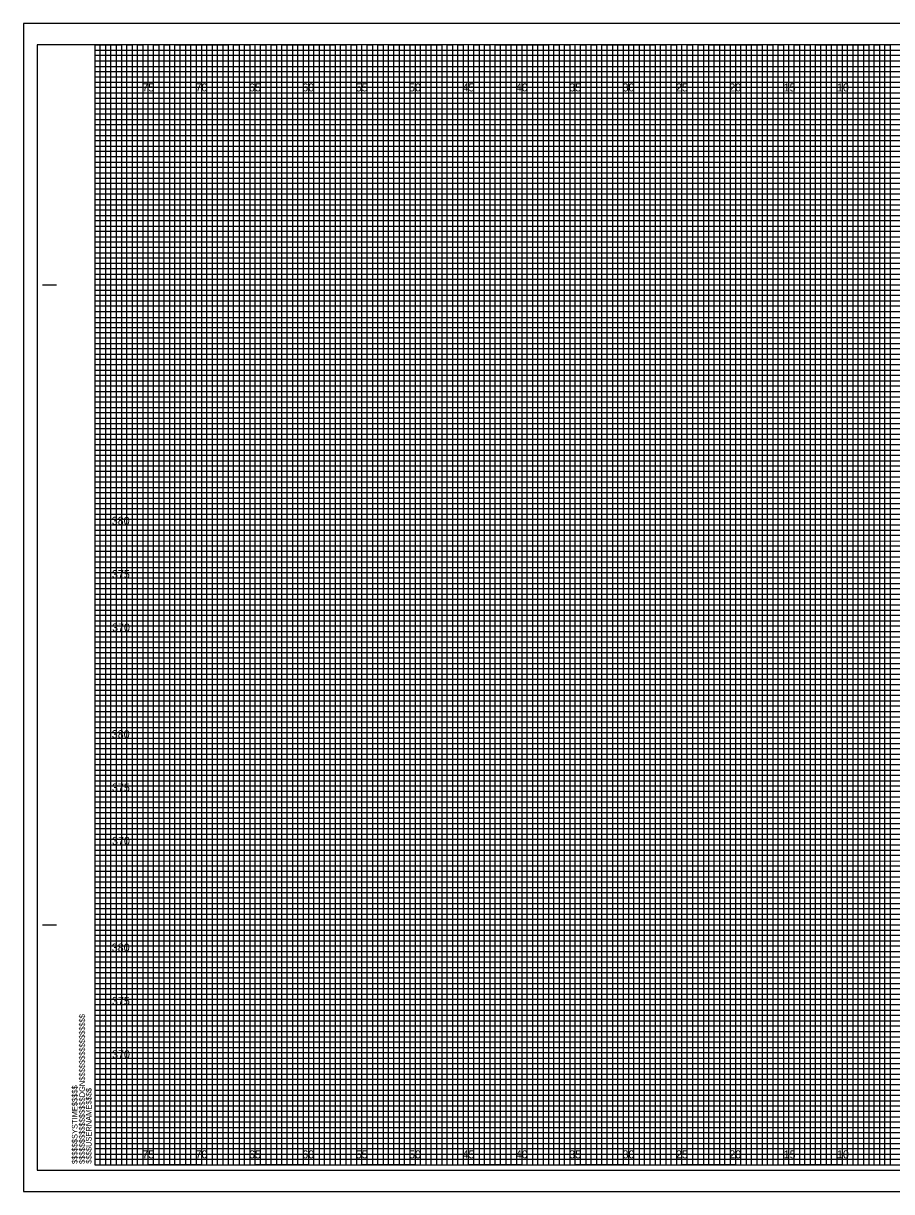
# Model space of a CAD drawing. Extents: x -7 to 162, y -2 to 327.
# Drawn here: x -6.7 to 74.6, y 217.5 to 327 of the extents above; entities that cross this region are included whole.
import ezdxf

# ---------------------------------------------------------------- set-up
doc = ezdxf.new("R2010")
doc.units = 0
for name, color, linetype in [('Exist Cross Section Cell', 7, 'Continuous'), ('Prop CMT Pvmt Course 1', 7, 'Continuous'), ('Prop CMT Pvmt Course 3', 7, 'Continuous'), ('Prop CMT Shld Paved Course 1', 7, 'Continuous'), ('Prop CMT Shld Paved Course 2', 7, 'Continuous'), ('Prop CMT Shld Paved Course 3', 7, 'Continuous'), ('Prop CMT Slope Grass', 7, 'Continuous'), ('Prop CMT Subgrade Earthwork', 7, 'Continuous'), ('Scratch_Level_3', 7, 'Continuous')]:
    doc.layers.add(name, color=color, linetype=linetype)

msp = doc.modelspace()

# ---------------------------------------------------------------- linework, layer by layer
at = {"layer": 'Prop CMT Pvmt Course 3'}
msp.add_lwpolyline([(-6.7, 217.5), (161.65, 217.5), (161.65, 327), (-6.7, 327)], close=True, dxfattribs=at)
at = {"layer": 'Prop CMT Shld Paved Course 1'}
for p, q in [((0, 324.5), (110.95, 324.5)), ((110.95, 323.99), (0, 323.99)), ((0, 323.99), (0, 323.5)), ((0, 323.5), (110.95, 323.5)), ((110.95, 322.94), (0, 322.94)), ((0, 322.94), (0, 322)), ((0, 322), (160, 322))]:
    msp.add_line(p, q, dxfattribs=at)
for points in [[(0, 321.5), (135, 321.5), (160, 321.5)], [(160, 321), (0, 321)], [(0, 320.5), (160, 320.5)], [(160, 319.5), (0, 319.5)], [(0, 319), (160, 319)], [(160, 318.5), (0, 318.49)], [(0, 318), (160, 318)], [(160, 317), (0, 317)], [(0, 316.5), (160, 316.5), (160, 316), (0, 316)], [(0, 315.5), (160, 315.5), (160, 314.5), (0, 314.5)], [(0, 314), (160, 314), (160, 313.5), (0, 313.5)], [(0, 313), (160, 313), (160, 312), (0, 312)], [(0, 311.5), (160, 311.5), (160, 311), (0, 311)], [(0, 310.5), (160, 310.5), (160, 309.5), (0, 309.5)], [(0, 309), (160, 309), (160, 308.5), (0, 308.5)], [(0, 308), (160, 308), (160, 306.97), (160, 306.5), (160, 306), (0, 306)], [(0, 307), (160, 307), (160, 306.5), (0, 306.5)], [(0, 305.5), (160, 305.5), (160, 304.5), (0, 304.51)], [(0, 304.51), (160, 304.5), (160, 304), (0, 304)], [(0, 303.5), (160, 303.5), (160, 303), (0, 303)], [(0, 302), (160, 302), (160, 301.5), (0, 301.5)], [(0, 301), (160, 301), (160, 300.5), (0, 300.5)], [(-0.04, 299.44), (160, 299.44), (160, 298.94), (-0.04, 298.94)], [(0, 298.5), (160, 298.5), (160, 298), (0, 298)], [(0, 297), (160, 297), (160, 296.5), (0, 296.5)], [(0, 296), (160, 296), (160, 295.5), (0, 295.5)], [(0, 294.5), (160, 294.5), (160, 294), (0, 294)], [(0, 293.5), (160, 293.5), (160, 293), (0, 293)], [(0, 292), (160, 292), (160, 291.5), (0, 291.5)], [(0, 291), (160, 291), (160, 290.5), (0, 290.5)], [(0, 289.5), (160, 289.5), (159.99, 288.99), (0, 289)], [(0, 288.5), (160, 288.5), (160, 288), (0, 288)], [(0, 287), (160, 287), (160, 286.5), (0, 286.5)], [(0, 286), (160, 286), (160, 285.5), (0, 285.5)], [(0, 284.5), (160, 284.5), (160, 284), (0, 284)], [(0, 283.5), (160, 283.5), (160, 283), (0, 283)], [(0, 282), (160, 282), (160, 281.5), (0, 281.5)], [(0, 281), (160, 281), (160, 280.5), (0, 280.5)], [(0, 279.5), (160, 279.5), (160, 279), (0, 279)], [(0, 278.5), (160.03, 278.45), (160, 278), (0, 278)], [(0, 277), (160, 277), (160, 276.5), (0, 276.5)], [(0, 276), (160, 276), (160, 275.5), (0, 275.5)], [(0, 274.5), (160, 274.5), (160, 274), (0, 274)], [(0, 273.5), (160, 273.5), (160, 273), (0, 273)], [(0, 272), (160, 272), (160, 271.5), (0, 271.5)], [(0, 271), (160, 271), (160, 270.5), (0, 270.5)], [(0, 269.5), (160, 269.5), (160, 269), (0, 269)], [(0, 268.5), (160, 268.5), (160, 268), (0, 268)], [(0, 267), (160, 267), (160, 266.5), (0, 266.5)], [(0, 266), (160, 266), (160, 265.5), (0, 265.5)], [(0, 264.5), (160, 264.5), (160, 264), (0, 264)], [(0, 263.5), (160, 263.5), (160, 263), (0, 263)], [(0, 262), (160, 262), (160, 261.5), (0, 261.5)], [(0, 261), (160, 261), (160, 260.5), (0, 260.5)], [(0, 259.5), (160, 259.5), (159.99, 258.99), (0, 259)], [(0, 258.5), (160, 258.5), (160, 258), (0, 258)], [(0, 257), (160, 257), (160, 256.5), (0, 256.5)], [(0, 256), (160, 256), (160, 255.5), (0, 255.5)], [(0, 254.5), (160, 254.5), (160, 254), (0, 254)], [(0, 253.5), (160, 253.5), (160, 253), (0, 253)], [(0, 252), (160, 252), (160, 251.5), (0, 251.5)], [(0, 251), (160, 251), (160, 250.5), (0, 250.5)], [(0, 249.5), (160, 249.5), (160, 249), (0, 249)], [(0, 248.5), (160.03, 248.46), (160, 248), (0, 248)], [(0, 247), (160, 247), (160, 246.5), (0, 246.5)], [(0, 246), (160, 246), (160, 245.5), (0, 245.5)], [(0, 244.5), (160, 244.5), (160, 244), (0, 244)], [(0, 243.5), (160, 243.5), (160, 243), (0, 243)], [(0, 242), (160, 242), (160, 241.5), (0, 241.5)], [(0, 241), (160, 241), (160, 240.5), (0, 240.5)], [(0, 239.5), (160, 239.5), (160, 239), (0, 239)], [(0, 238.5), (160, 238.5), (160, 238), (0, 238)], [(0, 237), (160, 237), (160, 236.5), (0, 236.5)], [(0, 236), (160, 236), (160, 235.5), (0, 235.5)], [(0, 234.5), (160, 234.5), (160, 234), (0, 234)], [(0, 233.5), (160, 233.5), (160, 233), (0, 233)], [(0, 232), (160, 232), (160, 231.5), (0, 231.5)], [(0, 231), (160, 231), (160, 230.5), (0, 230.5)], [(0, 229.5), (160, 229.5), (160, 229), (0, 229)], [(0, 228.5), (160, 228.5), (160, 228), (0, 228)], [(0, 227), (160, 227), (160, 226.5), (0, 226.5)], [(0, 226), (160, 226), (160, 225.5), (0, 225.5)], [(0, 224.5), (160, 224.5), (160, 224), (0, 224)], [(0, 223.5), (160, 223.5), (160, 223), (0, 223)], [(0, 222), (160, 222), (160, 221.5), (0, 221.5)], [(0, 221), (160, 221), (160, 220.5), (0, 220.5)]]:
    msp.add_lwpolyline(points, dxfattribs=at)
at = {"layer": 'Prop CMT Shld Paved Course 2'}
for p, q in [((-4.9, 302.5), (-3.65, 302.5)), ((-4.85, 302.5), (-3.6, 302.5)), ((-4.9, 242.5), (-3.65, 242.5)), ((-4.85, 242.5), (-3.6, 242.5)), ((0, 220), (0, 220)), ((0, 220), (0, 220)), ((0, 220), (0, 220)), ((0, 220), (0, 220)), ((0, 220), (0, 220)), ((0, 220), (0, 220)), ((0, 220), (0, 220))]:
    msp.add_line(p, q, dxfattribs=at)
msp.add_lwpolyline([(160, 325), (0, 325), (0, 220), (160, 220)], close=True, dxfattribs=at)
at = {"layer": 'Prop CMT Shld Paved Course 3'}
for points in [[(0, 220), (0.5, 220), (0.5, 325), (1, 325), (1, 220)], [(1, 220), (1.5, 220), (1.5, 325), (2, 325), (2, 220)], [(2.5, 220), (3, 220), (3, 325), (3.5, 325), (3.5, 220)], [(3.5, 220), (4, 220), (4, 325), (4.5, 325), (4.5, 220)], [(5, 220), (5.5, 220), (5.5, 325), (6, 325), (6, 220)], [(6, 220), (6.5, 220), (6.5, 325), (7, 325), (7, 220)], [(7.5, 220), (8, 220), (8, 325), (8.5, 325), (8.5, 220)], [(8.5, 220), (9, 220), (9, 325), (9.5, 325), (9.5, 220)], [(10, 220), (10.5, 220), (10.5, 325), (11, 325), (11, 220)], [(11, 220), (11.5, 220), (11.5, 325), (12, 325), (12, 220)], [(12.5, 220), (13, 220), (13, 325), (13.5, 325), (13.5, 220)], [(13.5, 220), (14, 220), (14, 325), (14.5, 325), (14.5, 220)], [(15, 220), (15.5, 220), (15.5, 325), (16, 325), (16, 220)], [(16, 220), (16.5, 220), (16.5, 325), (17, 325), (17, 220)], [(17.5, 220), (18, 220), (18, 325), (18.5, 325), (18.5, 220)], [(18.5, 220), (19, 220), (19, 325), (19.5, 325), (19.5, 220)], [(20, 220), (20.5, 220), (20.5, 325), (21, 325), (21, 220)], [(21, 220), (21.5, 220), (21.5, 325), (22, 325), (22, 220)], [(22.5, 220), (23, 220), (23, 325), (23.5, 325), (23.5, 220)], [(23.5, 220), (24, 220), (24, 325), (24.5, 325), (24.5, 220)], [(25, 220), (25.5, 220), (25.5, 325), (26, 325), (26, 220)], [(26, 220), (26.5, 220), (26.5, 325), (27, 325), (27, 220)], [(27.5, 220), (28, 220), (28, 325), (28.5, 325), (28.5, 220)], [(28.5, 220), (29, 220), (29, 325), (29.5, 325), (29.5, 220)], [(30, 220), (30.5, 220), (30.5, 325), (31, 325), (31, 220)], [(31, 220), (31.5, 220), (31.5, 325), (32, 325), (32, 220)], [(32.5, 220), (33, 220), (33, 325), (33.5, 325), (33.5, 220)], [(33.5, 220), (34, 220), (34, 325), (34.5, 325), (34.5, 220)], [(35, 220), (35.5, 220), (35.5, 325), (36, 325), (36, 220)], [(36, 220), (36.5, 220), (36.5, 325), (37, 325), (37, 220)], [(37.5, 220), (38, 220), (38, 325), (38.5, 325), (38.5, 220)], [(38.5, 220), (39, 220), (39, 325), (39.5, 325), (39.5, 220)], [(40, 220), (40.5, 220), (40.5, 325), (41, 325), (41, 220)], [(41, 220), (41.5, 220), (41.5, 325), (42, 325), (42, 220)], [(42.5, 220), (43, 220), (43, 325), (43.5, 325), (43.5, 220)], [(43.5, 220), (44, 220), (44, 325), (44.5, 325), (44.5, 220)], [(45, 220), (45.5, 220), (45.5, 325), (46, 325), (46, 220)], [(46, 220), (46.5, 220), (46.5, 325), (47, 325), (47, 220)], [(47.5, 220), (48, 220), (48, 325), (48.5, 325), (48.5, 220)], [(48.5, 220), (49, 220), (49, 325), (49.5, 325), (49.5, 220)], [(50, 220), (50.5, 220), (50.5, 325), (51, 325), (51, 220)], [(51, 220), (51.5, 220), (51.5, 325), (52, 325), (52, 220)], [(52.5, 220), (53, 220), (53, 325), (53.5, 325), (53.5, 220)], [(53.5, 220), (54, 220), (54, 325), (54.5, 325), (54.5, 220)], [(55, 220), (55.5, 220), (55.5, 325), (56, 325), (56, 220)], [(56, 220), (56.5, 220), (56.5, 325), (57, 325), (57, 220)], [(57.5, 220), (58, 220), (58, 325), (58.5, 325), (58.5, 220)], [(58.5, 220), (59, 220), (59, 325), (59.5, 325), (59.5, 220)], [(60, 220), (60.5, 220), (60.5, 325), (61, 325), (61, 220)], [(61, 220), (61.5, 220), (61.5, 325), (62, 325), (62, 220)], [(62.5, 220), (63, 220), (63, 325), (63.5, 325), (63.5, 220)], [(63.5, 220), (64, 220), (64, 325), (64.5, 325), (64.5, 220)], [(65, 220), (65.5, 220), (65.5, 325), (66, 325), (66, 220)], [(66, 220), (66.5, 220), (66.5, 325), (67, 325), (67, 220)], [(67.5, 220), (68, 220), (68, 325), (68.5, 325), (68.5, 220)], [(68.5, 220), (69, 220), (69, 325), (69.5, 325), (69.5, 220)], [(70, 220), (70.5, 220), (70.5, 325), (71, 325), (71, 220)], [(71, 220), (71.5, 220), (71.5, 325), (72, 325), (72, 220)], [(72.5, 220), (73, 220), (73, 325), (73.5, 325), (73.5, 220)], [(73.5, 220), (74, 220), (74, 325), (74.5, 325), (74.5, 220)]]:
    msp.add_lwpolyline(points, dxfattribs=at)
at = {"layer": 'Prop CMT Slope Grass'}
for points in [[(0, 325), (2.5, 325), (2.5, 220), (7.5, 220), (7.5, 325), (12.5, 325), (12.5, 220), (17.5, 220), (17.5, 325), (22.5, 325), (22.5, 220), (27.5, 220), (27.5, 325), (32.5, 325), (32.5, 220), (37.5, 220), (37.5, 325), (42.5, 325), (42.5, 220), (47.5, 220), (47.5, 325), (52.5, 325), (52.5, 220), (57.5, 220), (57.5, 325), (62.5, 325), (62.5, 220), (67.5, 220), (67.5, 325), (72.5, 325), (72.5, 220), (77.5, 220)], [(0, 322.5), (137.5, 322.5)], [(0, 312.5), (160, 312.5), (160, 322.5)], [(160, 317.5), (0, 317.5)], [(0, 302.5), (160, 302.5), (160, 307.5), (0, 307.5)], [(0, 292.5), (160, 292.5), (160, 297.5), (0, 297.5)], [(0, 282.5), (160, 282.5), (160, 287.5), (0, 287.5)], [(0, 272.5), (160, 272.5), (160, 277.5), (0, 277.5)], [(0, 262.5), (160, 262.5), (160, 267.5), (0, 267.5)], [(0, 252.5), (160, 252.5), (160, 257.5), (0, 257.5)], [(0, 242.5), (160, 242.5), (160, 247.5), (0, 247.5)], [(0, 232.5), (160, 232.5), (160, 237.5), (0, 237.5)], [(0, 222.5), (160, 222.5), (160, 227.5), (0, 227.5)]]:
    msp.add_lwpolyline(points, dxfattribs=at)
at = {"layer": 'Prop CMT Subgrade Earthwork'}
msp.add_lwpolyline([(-5.4, 219.5), (161.2, 219.5), (161.2, 325), (-5.4, 325)], close=True, dxfattribs=at)
at = {"layer": 'Scratch_Level_3'}
for p, q in [((5, 325), (0, 325)), ((5, 220), (5, 325)), ((15, 325), (10, 325)), ((10, 325), (10, 220)), ((15, 220), (15, 325)), ((25, 325), (20, 325)), ((20, 325), (20, 220)), ((25, 220), (25, 325)), ((35, 325), (30, 325)), ((30, 325), (30, 220)), ((35, 220), (35, 325)), ((45, 325), (40, 325)), ((40, 325), (40, 220)), ((45, 220), (45, 325)), ((55, 325), (50, 325)), ((50, 325), (50, 220)), ((55, 220), (55, 325)), ((65, 325), (60, 325)), ((60, 325), (60, 220)), ((65, 220), (65, 325)), ((75, 325), (70, 325)), ((70, 325), (70, 220)), ((10, 220), (5, 220)), ((20, 220), (15, 220)), ((30, 220), (25, 220)), ((40, 220), (35, 220)), ((50, 220), (45, 220)), ((60, 220), (55, 220)), ((70, 220), (65, 220))]:
    msp.add_line(p, q, dxfattribs=at)
for points in [[(160, 322.5), (160, 315), (0, 315)], [(0, 320), (160, 320)], [(0, 310), (160, 310), (160, 305), (0, 305)], [(0, 300), (160, 300), (160, 295), (0, 295)], [(0, 290), (160, 290), (160, 285), (0, 285)], [(0, 280), (160, 280), (160, 275), (0, 275)], [(0, 270), (160, 270), (160, 265), (0, 265)], [(0, 260), (160, 260), (160, 255), (0, 255)], [(0, 250), (160, 250), (160, 245), (0, 245)], [(0, 240), (160, 240), (160, 235), (0, 235)], [(0, 230), (160, 230), (160, 225), (0, 225)]]:
    msp.add_lwpolyline(points, dxfattribs=at)

# ---------------------------------------------------------------- texts
at = {"layer": 'Exist Cross Section Cell'}
for s, p in [('75', (4.44, 320.62)), ('70', (9.43, 320.62)), ('65', (14.44, 320.62)), ('60', (19.43, 320.62)), ('55', (24.44, 320.62)), ('50', (29.43, 320.62)), ('45', (34.44, 320.62)), ('40', (39.43, 320.62)), ('35', (44.44, 320.62)), ('30', (49.43, 320.62)), ('25', (54.44, 320.62)), ('20', (59.43, 320.62)), ('15', (64.53, 320.62)), ('10', (69.52, 320.62)), ('75', (4.44, 220.62)), ('70', (9.43, 220.62)), ('65', (14.44, 220.62)), ('60', (19.43, 220.62)), ('55', (24.44, 220.62)), ('50', (29.43, 220.62)), ('45', (34.44, 220.62)), ('40', (39.43, 220.62)), ('35', (44.44, 220.62)), ('30', (49.43, 220.62)), ('25', (54.44, 220.62)), ('20', (59.43, 220.62)), ('15', (64.53, 220.62)), ('10', (69.52, 220.62))]:
    msp.add_text(s, height=0.75, dxfattribs=at).set_placement(p)
at = {"layer": 'Prop CMT Pvmt Course 1'}
for s, p in [('380', (1.58, 280)), ('375', (1.6, 275)), ('370', (1.61, 270)), ('380', (1.58, 260)), ('375', (1.6, 255)), ('370', (1.61, 250)), ('380', (1.58, 240)), ('375', (1.6, 235)), ('370', (1.61, 230))]:
    msp.add_text(s, height=0.75, dxfattribs=at).set_placement(p)
at = {"layer": 'Prop CMT Shld Paved Course 2'}
for s, p in [('$$$$$$$$$$$$$$$$DGN$$$$$$$$$$$$$$$$', (-0.94, 220.09)), ('$$$$$$SYSTIME$$$$$', (-1.63, 220.09)), ('$$$$USERNAME$$$$', (-0.31, 220.12))]:
    msp.add_text(s, height=0.525, rotation=90, dxfattribs=at).set_placement(p)

doc.saveas('drawing.dxf')
